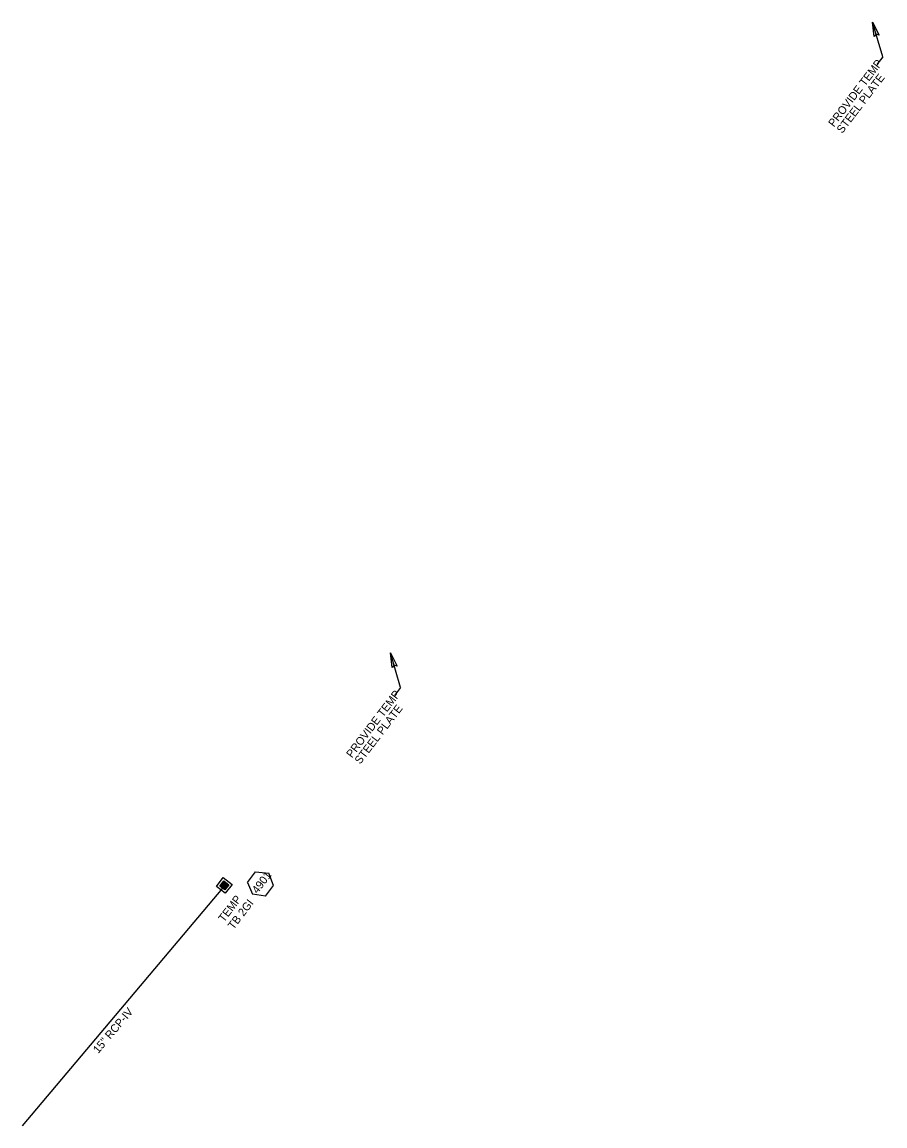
# Model space of a CAD drawing. Extents: x 2214978 to 2238755, y 984122 to 1016255.
# Drawn here: x 2227017 to 2227556, y 997496 to 998186 of the extents above; entities that cross this region are included whole.
import ezdxf

# ---------------------------------------------------------------- set-up
doc = ezdxf.new("R2010")
doc.units = 0
for name, color, linetype in [('Prop Drainage Structure Box Number Symbol CELL', 7, 'Continuous'), ('Prop Drainage Structure Drop Inlet Grate 2 Wide Slots and Sag Grates 840 22 TB CELL', 7, 'Continuous'), ('Prop Drainage Structure Drop Inlet Grate 2 Wide Slots and Sag Grates 840 22 TB Label', 7, 'Continuous'), ('Prop Drainage Structure Pipe RCP 15in Class IV', 7, 'Continuous'), ('Prop Drainage Structure Pipe RCP 15in Class IV Label', 7, 'Continuous'), ('Prop Drainage Structure Plot Symbol 20 Scale', 7, 'Continuous'), ('Prop Drainage Structure Plot Symbol 50 Scale', 7, 'Continuous'), ('Prop Plan Preparation Drainage Notes Label', 7, 'Continuous')]:
    doc.layers.add(name, color=color, linetype=linetype)

msp = doc.modelspace()

# ---------------------------------------------------------------- linework, layer by layer
at = {"layer": 'Prop Drainage Structure Box Number Symbol CELL'}
for p, q in [((2227157.96, 997648.18), (2227163.06, 997654.85)), ((2227163.06, 997654.85), (2227171.32, 997653.91)), ((2227174.4, 997646.18), (2227171.32, 997653.91)), ((2227157.96, 997648.18), (2227161.19, 997640.78)), ((2227169.3, 997639.51), (2227174.4, 997646.18)), ((2227169.3, 997639.51), (2227161.19, 997640.78))]:
    msp.add_line(p, q, dxfattribs=at)
at = {"layer": 'Prop Drainage Structure Drop Inlet Grate 2 Wide Slots and Sag Grates 840 22 TB CELL'}
for p, q in [((2227142.33, 997644.64), (2227142.33, 997644.64)), ((2227142.62, 997646.94), (2227142.62, 997646.94)), ((2227143.55, 997646.23), (2227143.55, 997646.23)), ((2227144.48, 997645.52), (2227144.48, 997645.52)), ((2227144.76, 997647.82), (2227144.76, 997647.82))]:
    msp.add_line(p, q, dxfattribs=at)
for points in [[(2227145.69, 997647.11), (2227143.26, 997643.93), (2227141.41, 997645.35), (2227143.84, 997648.53), (2227145.69, 997647.11)], [(2227145.6, 997647.1), (2227143.25, 997644.02), (2227141.49, 997645.36), (2227143.85, 997648.44), (2227145.6, 997647.1), (2227145.6, 997647.1)], [(2227144.41, 997645.56), (2227143.25, 997644.03), (2227141.51, 997645.36), (2227142.67, 997646.89), (2227144.41, 997645.56)], [(2227142.43, 997645.81), (2227141.92, 997645.15), (2227141.71, 997645.31), (2227142.21, 997645.98), (2227142.43, 997645.81)], [(2227142.74, 997645.58), (2227142.23, 997644.92), (2227142.01, 997645.08), (2227142.52, 997645.74), (2227142.74, 997645.58)], [(2227142.99, 997646.54), (2227142.48, 997645.88), (2227142.27, 997646.04), (2227142.77, 997646.7), (2227142.99, 997646.54)], [(2227143.04, 997645.34), (2227142.54, 997644.68), (2227142.32, 997644.85), (2227142.83, 997645.51), (2227143.04, 997645.34)], [(2227143.29, 997646.31), (2227142.79, 997645.64), (2227142.57, 997645.81), (2227143.08, 997646.47), (2227143.29, 997646.31)], [(2227143.35, 997645.11), (2227142.84, 997644.45), (2227142.63, 997644.61), (2227143.13, 997645.27), (2227143.35, 997645.11)], [(2227145.59, 997647.1), (2227144.42, 997645.57), (2227142.69, 997646.9), (2227143.85, 997648.42), (2227145.59, 997647.1)], [(2227143.6, 997646.07), (2227143.09, 997645.41), (2227142.88, 997645.57), (2227143.38, 997646.24), (2227143.6, 997646.07)], [(2227143.61, 997647.35), (2227143.1, 997646.69), (2227142.89, 997646.85), (2227143.39, 997647.52), (2227143.61, 997647.35)], [(2227143.65, 997644.88), (2227143.15, 997644.21), (2227142.93, 997644.38), (2227143.44, 997645.04), (2227143.65, 997644.88)], [(2227143.91, 997645.84), (2227143.4, 997645.18), (2227143.18, 997645.34), (2227143.69, 997646), (2227143.91, 997645.84)], [(2227143.91, 997647.12), (2227143.41, 997646.46), (2227143.19, 997646.62), (2227143.7, 997647.28), (2227143.91, 997647.12)], [(2227144.16, 997648.08), (2227143.66, 997647.42), (2227143.44, 997647.58), (2227143.95, 997648.24), (2227144.16, 997648.08)], [(2227144.21, 997645.6), (2227143.71, 997644.94), (2227143.49, 997645.11), (2227144, 997645.77), (2227144.21, 997645.6)], [(2227144.22, 997646.88), (2227143.71, 997646.22), (2227143.5, 997646.39), (2227144, 997647.05), (2227144.22, 997646.88)], [(2227144.47, 997647.85), (2227143.96, 997647.18), (2227143.75, 997647.35), (2227144.25, 997648.01), (2227144.47, 997647.85)], [(2227144.53, 997646.65), (2227144.02, 997645.99), (2227143.8, 997646.15), (2227144.31, 997646.81), (2227144.53, 997646.65)], [(2227144.78, 997647.61), (2227144.27, 997646.95), (2227144.05, 997647.11), (2227144.56, 997647.78), (2227144.78, 997647.61)], [(2227144.83, 997646.42), (2227144.33, 997645.75), (2227144.11, 997645.92), (2227144.62, 997646.58), (2227144.83, 997646.42)], [(2227145.08, 997647.38), (2227144.58, 997646.72), (2227144.36, 997646.88), (2227144.87, 997647.54), (2227145.08, 997647.38)], [(2227145.39, 997647.14), (2227144.88, 997646.48), (2227144.67, 997646.65), (2227145.17, 997647.31), (2227145.39, 997647.14)]]:
    msp.add_lwpolyline(points, dxfattribs=at)
at = {"layer": 'Prop Drainage Structure Pipe RCP 15in Class IV'}
msp.add_line((2227142.33, 997644.64), (2227017.19, 997496.02), dxfattribs=at)
at = {"layer": 'Prop Drainage Structure Plot Symbol 20 Scale'}
msp.add_lwpolyline([(2227146.35, 997646.6), (2227143.92, 997643.43), (2227140.74, 997645.85), (2227143.17, 997649.03)], close=True, dxfattribs=at)
at = {"layer": 'Prop Drainage Structure Plot Symbol 50 Scale'}
msp.add_lwpolyline([(2227148.45, 997646.88), (2227144.2, 997641.32), (2227138.64, 997645.57), (2227142.89, 997651.14)], close=True, dxfattribs=at)
at = {"layer": 'Prop Plan Preparation Drainage Notes Label'}
for p, q in [((2227554.96, 998163.94), (2227548.68, 998185.59)), ((2227554.96, 998163.94), (2227551.21, 998159.04)), ((2227253.74, 997769.87), (2227247.46, 997791.51)), ((2227253.74, 997769.87), (2227249.99, 997764.96))]:
    msp.add_line(p, q, dxfattribs=at)
for points in [[(2227549.7, 998176.51), (2227548.68, 998185.59), (2227552.74, 998177.34), (2227550.88, 998178)], [(2227248.48, 997782.43), (2227247.46, 997791.51), (2227251.52, 997783.26), (2227249.66, 997783.92)]]:
    msp.add_lwpolyline(points, close=True, dxfattribs=at)

# ---------------------------------------------------------------- texts
at = {"layer": 'Prop Drainage Structure Box Number Symbol CELL'}
msp.add_text('4901', height=5, rotation=52.6073, dxfattribs=at).set_placement((2227164.3, 997640.75))
at = {"layer": 'Prop Drainage Structure Drop Inlet Grate 2 Wide Slots and Sag Grates 840 22 TB Label'}
for s, p in [('TEMP', (2227143.36, 997622.89)), ('TB 2GI', (2227149.32, 997618.34))]:
    msp.add_text(s, height=5, rotation=52.6073, dxfattribs=at).set_placement(p)
at = {"layer": 'Prop Drainage Structure Pipe RCP 15in Class IV Label'}
msp.add_text('15" RCP-IV ', height=5, rotation=49.90157, dxfattribs=at).set_placement((2227064.81, 997540.93))
at = {"layer": 'Prop Plan Preparation Drainage Notes Label'}
for s, p in [('PROVIDE TEMP', (2227524.49, 998119.66)), ('STEEL PLATE', (2227529.7, 998115.68)), ('PROVIDE TEMP', (2227223.27, 997725.58)), ('STEEL PLATE', (2227228.48, 997721.61))]:
    msp.add_text(s, height=5, rotation=52.62119, dxfattribs=at).set_placement(p)

doc.saveas('drawing.dxf')
